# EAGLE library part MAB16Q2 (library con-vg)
CONNECTOR male, 16 pins, type Q/2, rows AB, grid 2.54 mm / 5.08 mm
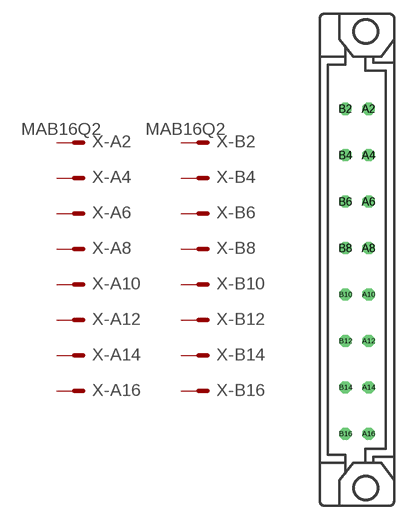
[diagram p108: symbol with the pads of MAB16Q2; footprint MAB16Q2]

Designator prefix X; gates -A2=MVAL -A4=MAL -A6=MAL -A8=MAL -A10=MAL -A12=MAL -A14=MAL -A16=MAL -B2=MVAL -B4=MAL -B6=MAL -B8=MAL -B10=MAL -B12=MAL -B14=MAL -B16=MAL

## MAB16Q2  [MAB16Q2]
A2  -A2:S  pas
A4  -A4:S  pas
A6  -A6:S  pas
A8  -A8:S  pas
A10  -A10:S  pas
A12  -A12:S  pas
A14  -A14:S  pas
A16  -A16:S  pas
B2  -B2:S  pas
B4  -B4:S  pas
B6  -B6:S  pas
B8  -B8:S  pas
B10  -B10:S  pas
B12  -B12:S  pas
B14  -B14:S  pas
B16  -B16:S  pas

## Footprint MAB16Q2 (pad centres in mm)
CONNECTOR male, 16 pins, type Q/2, rows AB, grid 2.54 mm / 5.08 mm
drill 0.813 octagon: A2 1.27,16.51; A4 1.27,11.43; A6 1.27,6.35; A8 1.27,1.27; A10 1.27,-3.81; A12 1.27,-8.89; A14 1.27,-13.97; A16 1.27,-19.05; B2 -1.27,16.51; B4 -1.27,11.43; B6 -1.27,6.35; B8 -1.27,1.27; B10 -1.27,-3.81; B12 -1.27,-8.89; B14 -1.27,-13.97; B16 -1.27,-19.05
hole 2.794 at 0.965,-25
hole 2.794 at 0.965,25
